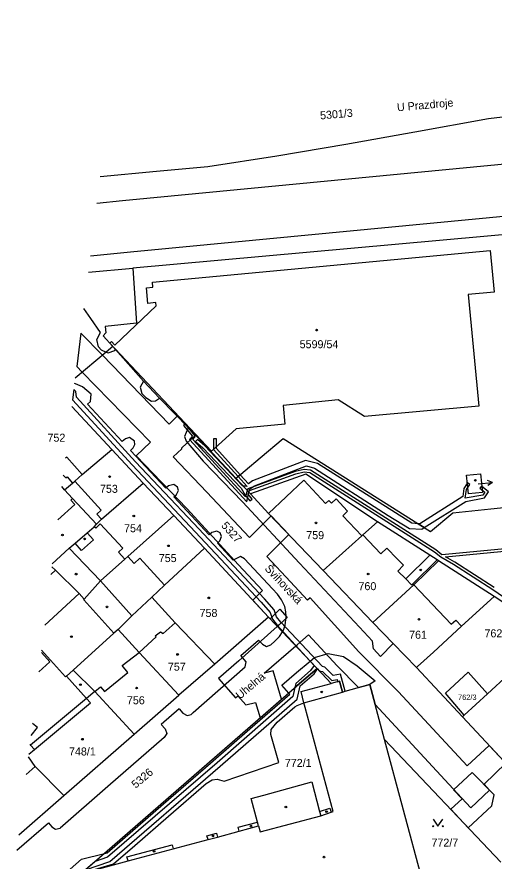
# Model space of a CAD drawing. Extents: x -821458 to -820266, y -1071458 to -1069826.
# Drawn here: x -821418.8 to -821317.4, y -1070028.3 to -1069849 of the extents above; entities that cross this region are included whole.
import ezdxf

# ---------------------------------------------------------------- set-up
doc = ezdxf.new("R2010")
doc.units = 0
for name, color, linetype in [('Vrstva 1', 7, 'Continuous'), ('Vrstva 13', 7, 'Continuous'), ('Vrstva 2', 7, 'Continuous'), ('Vrstva 3', 7, 'Continuous'), ('Vrstva 4', 7, 'Continuous'), ('Vrstva 5', 7, 'Continuous'), ('Vrstva 7', 7, 'Continuous')]:
    doc.layers.add(name, color=color, linetype=linetype)

msp = doc.modelspace()

# ---------------------------------------------------------------- linework, layer by layer
at = {"layer": 'Vrstva 1'}
for p, q in [((-821403.61, -1069903.25), (-821394.16, -1069902.36)), ((-821391.95, -1069948.02), (-821398.62, -1069940.91)), ((-821391.95, -1069948.02), (-821385.42, -1069954.95)), ((-821369.19, -1069950.3), (-821372.25, -1069947.02)), ((-821385.42, -1069954.95), (-821378.92, -1069961.87)), ((-821378.92, -1069961.87), (-821365.36, -1069976.5)), ((-821410.59, -1069966.54), (-821411.34, -1069965.82)), ((-821317.44, -1069972.1), (-821329.25, -1069964.52)), ((-821405.55, -1069971.52), (-821410.59, -1069966.54)), ((-821353.75, -1069966.62), (-821343.18, -1069977.68)), ((-821404.47, -1069972.7), (-821405.55, -1069971.52)), ((-821305.58, -1069979.99), (-821317.44, -1069972.1)), ((-821365.36, -1069976.5), (-821376.77, -1069986.5)), ((-821397.28, -1069979.17), (-821398.18, -1069979.89)), ((-821376.77, -1069986.5), (-821384.37, -1069993.11)), ((-821352.01, -1069990.61), (-821355.04, -1069987.4)), ((-821333.94, -1069987.23), (-821324.17, -1069997.7)), ((-821393.85, -1070001.36), (-821402.26, -1069992.33)), ((-821393.85, -1070001.36), (-821384.37, -1069993.11)), ((-821323.76, -1069997.32), (-821318.87, -1069992.82)), ((-821324.17, -1069997.7), (-821323.76, -1069997.32)), ((-821324.17, -1069997.7), (-821315.23, -1070007.23)), ((-821408.79, -1070014.39), (-821393.85, -1070001.36)), ((-821332.49, -1070033), (-821340.69, -1070002.53)), ((-821340.69, -1070002.53), (-821315.99, -1070028.55)), ((-821418.38, -1070022.73), (-821408.79, -1070014.39))]:
    msp.add_line(p, q, dxfattribs=at)
for points in [[(-821401.79, -1069888.55), (-821396.38, -1069888.03), (-821301.11, -1069878.88), (-821163.06, -1069864.6), (-821108.67, -1069859.31), (-821104.19, -1069858.87), (-821101.19, -1069858.58), (-821096.14, -1069858.08), (-821092.87, -1069856.06), (-821092.18, -1069852.96), (-821094.27, -1069849.73), (-821097.25, -1069848.99), (-821101.9, -1069849.39), (-821105.19, -1069849.71), (-821109.73, -1069850.16), (-821251.45, -1069864.02), (-821303.1, -1069868.83), (-821318.66, -1069870.67)], [(-821318.66, -1069870.67), (-821334.3, -1069873.5), (-821348.89, -1069876.11), (-821363.55, -1069878.57), (-821378.22, -1069880.82), (-821389.11, -1069881.81), (-821401.09, -1069882.94)], [(-821285.17, -1069885.29), (-821310.26, -1069890.87), (-821394.68, -1069899), (-821403.18, -1069899.82)], [(-821274.54, -1069891.39), (-821310.18, -1069894.83), (-821394.16, -1069902.36)], [(-821372.25, -1069947.02), (-821371.7, -1069946.55), (-821370.31, -1069945.37), (-821367.11, -1069942.65), (-821362.25, -1069938.53), (-821330.97, -1069958.32), (-821326.19, -1069954.35), (-821318.1, -1069953.51), (-821272.71, -1069948.78), (-821270.2, -1069948.52), (-821272.6, -1069916.85), (-821273.51, -1069904.81), (-821274.54, -1069891.39)], [(-821377.42, -1069941.26), (-821399.04, -1069918.28), (-821398.71, -1069917.97), (-821397.99, -1069918.75), (-821389.2, -1069910.41), (-821389.28, -1069909.67), (-821390.98, -1069909.85), (-821391.29, -1069906.56), (-821389.89, -1069906.42), (-821390.01, -1069905.33), (-821318.28, -1069898.6), (-821317.44, -1069907.44), (-821322.92, -1069907.95), (-821320.7, -1069931.68), (-821344.94, -1069933.92), (-821350.55, -1069930.35), (-821362.21, -1069931.55), (-821361.85, -1069935.51), (-821372.24, -1069936.49), (-821377.42, -1069941.26)], [(-821394.16, -1069902.36), (-821393.38, -1069914.05), (-821400.03, -1069914.8), (-821399.89, -1069916.08), (-821400.48, -1069916.76), (-821398.4, -1069918.99)], [(-821398.4, -1069918.99), (-821399.83, -1069920.19), (-821406.39, -1069925.76)], [(-821372.25, -1069947.02), (-821382.15, -1069936.43), (-821382.32, -1069936.26), (-821388.41, -1069930.08), (-821388.48, -1069930.01), (-821391.9, -1069926.38), (-821391.91, -1069926.37), (-821397.82, -1069919.65), (-821398.4, -1069918.99)], [(-821398.62, -1069940.91), (-821407.13, -1069931.73)], [(-821408.64, -1069949.45), (-821406.97, -1069948.02), (-821406.5, -1069947.6), (-821404.9, -1069946.18), (-821398.62, -1069940.91)], [(-821342.21, -1069956.25), (-821357.45, -1069946.12), (-821369.19, -1069950.3)], [(-821323.29, -1069946.33), (-821320.32, -1069946.04), (-821319.9, -1069950.01), (-821322.87, -1069950.32), (-821323.29, -1069946.33)], [(-821401.91, -1069956.78), (-821400.79, -1069955.71), (-821391.95, -1069948.02)], [(-821408.64, -1069949.45), (-821409.23, -1069948.73)], [(-821401.91, -1069956.78), (-821406.94, -1069951.3), (-821408.64, -1069949.45)], [(-821369.19, -1069950.3), (-821365.33, -1069954.47), (-821353.75, -1069966.62)], [(-821404.47, -1069972.7), (-821401.05, -1069968.8), (-821395.89, -1069964.17), (-821395.23, -1069963.62), (-821385.42, -1069954.95)], [(-821411.26, -1069965.17), (-821407.65, -1069961.87), (-821406.42, -1069960.8), (-821403.85, -1069958.63), (-821402.38, -1069957.29), (-821401.91, -1069956.78)], [(-821353.75, -1069966.62), (-821345.55, -1069959.22), (-821345.34, -1069959.01), (-821342.21, -1069956.25)], [(-821329.25, -1069964.52), (-821329.56, -1069964.32), (-821331.11, -1069963.33), (-821342.21, -1069956.25)], [(-821390.1, -1069972.3), (-821387.4, -1069969.7), (-821378.92, -1069961.87)], [(-821343.18, -1069977.68), (-821334.5, -1069969.62), (-821329.25, -1069964.52)], [(-821405.55, -1069971.52), (-821412.87, -1069978.21)], [(-821398.18, -1069979.89), (-821404.58, -1069972.8), (-821404.47, -1069972.7)], [(-821397.28, -1069979.17), (-821394.4, -1069976.2), (-821390.1, -1069972.3)], [(-821376.77, -1069986.5), (-821385.2, -1069977.7), (-821390.1, -1069972.3)], [(-821333.94, -1069987.23), (-821333.72, -1069987.03), (-821330.34, -1069983.93), (-821324.37, -1069978.44), (-821317.44, -1069972.1)], [(-821355.04, -1069987.4), (-821356.49, -1069985.87), (-821362.4, -1069979.62), (-821365.36, -1069976.5)], [(-821343.18, -1069977.68), (-821338.9, -1069982.11), (-821333.94, -1069987.23)], [(-821398.18, -1069979.89), (-821406.81, -1069987.74), (-821402.26, -1069992.33)], [(-821384.37, -1069993.11), (-821392.8, -1069984), (-821397.28, -1069979.17)], [(-821318.87, -1069992.82), (-821314.37, -1069988.68), (-821313.66, -1069988.01), (-821312.67, -1069987.07), (-821312.75, -1069986.99), (-821307.81, -1069982.16)], [(-821355.04, -1069987.4), (-821361.05, -1069992.64), (-821400.19, -1070026.71), (-821404.92, -1070030.82), (-821404.89, -1070030.92)], [(-821323.76, -1069997.32), (-821327.76, -1069992.69), (-821322.93, -1069988.19), (-821318.87, -1069992.82)], [(-821404.89, -1070030.92), (-821402.96, -1070030.39), (-821395.18, -1070028.26), (-821395.4, -1070027.44), (-821385.84, -1070024.9), (-821385.62, -1070025.72), (-821378.18, -1070023.74), (-821378.43, -1070022.94), (-821376.42, -1070022.4), (-821376.21, -1070023.22), (-821371.58, -1070021.98), (-821371.8, -1070021.15), (-821367.67, -1070020.04), (-821369.02, -1070015.05), (-821366.37, -1070014.32), (-821356.12, -1070011.49), (-821354.5, -1070017.79), (-821352.33, -1070017.08), (-821352.03, -1070017.97), (-821351.61, -1070017.83), (-821357.55, -1069995.73), (-821357.82, -1069994.73), (-821358.41, -1069992.32), (-821352.01, -1069990.61)], [(-821340.69, -1070002.53), (-821343.84, -1069990.8), (-821349.65, -1069992.42), (-821350.27, -1069990.14), (-821352.01, -1069990.61)], [(-821402.26, -1069992.33), (-821404.01, -1069993.8), (-821415.89, -1070003.68), (-821416.04, -1070003.8)], [(-821415.77, -1070001.64), (-821414.38, -1069999.94), (-821415.46, -1069999.13)], [(-821408.79, -1070014.39), (-821414.88, -1070008.21), (-821416.33, -1070006.21)]]:
    msp.add_lwpolyline(points, dxfattribs=at)
at = {"layer": 'Vrstva 13'}
for p, q in [((-821405.2, -1069916.17), (-821406.08, -1069923.26)), ((-821406.68, -1069928.15), (-821406.95, -1069930.33))]:
    msp.add_line(p, q, dxfattribs=at)
for points in [[(-821315.23, -1070007.23), (-821318.46, -1070003.79), (-821323.18, -1070008.11), (-821337.71, -1069992.41), (-821346.16, -1069983.88), (-821356.51, -1069972.43), (-821357.04, -1069972.88), (-821360.66, -1069969), (-821365.69, -1069963.6), (-821361.05, -1069958.96), (-821364.8, -1069955.02), (-821369.41, -1069959.62), (-821378.44, -1069949.97), (-821385.56, -1069942.43), (-821383.76, -1069940.73), (-821383.76, -1069940.51), (-821380.85, -1069937.82), (-821382.15, -1069936.43), (-821382.32, -1069936.26), (-821384.71, -1069933.83), (-821386.41, -1069935.5), (-821400.63, -1069920.87), (-821405.2, -1069916.17)], [(-821406.08, -1069923.26), (-821404.89, -1069924.49), (-821390.44, -1069939.36), (-821393.46, -1069942.27), (-821382.72, -1069953.45), (-821371.72, -1069965.41), (-821366.65, -1069970.87), (-821368.68, -1069972.92), (-821365.36, -1069976.5), (-821365.01, -1069976.87), (-821362.97, -1069974.82), (-821361.35, -1069976.57), (-821363.11, -1069978.14), (-821363.48, -1069978.48), (-821371.67, -1069985.81), (-821375.97, -1069989.56), (-821372.38, -1069993.68), (-821371.86, -1069993.22), (-821370.17, -1069995.16), (-821368.13, -1069994.62), (-821367.11, -1069997.91), (-821362.56, -1069993.96), (-821364.39, -1069987.89), (-821366.28, -1069988.4), (-821359.55, -1069982.63), (-821359.26, -1069982.38), (-821356.87, -1069980.26), (-821350.73, -1069986.88), (-821346.23, -1069991.47), (-821343.84, -1069990.8), (-821342.7, -1069995.04), (-821325.26, -1070013.87), (-821322.38, -1070016.99), (-821318.38, -1070013.29), (-821319.57, -1070012), (-821314.95, -1070007.52)], [(-821406.95, -1069930.33), (-821394.3, -1069944.17), (-821382, -1069957.24), (-821366.94, -1069973.3), (-821365.01, -1069975.49), (-821364.5, -1069976.91), (-821363.5, -1069978.2), (-821356.49, -1069985.87), (-821355.65, -1069986.76), (-821356.42, -1069987.84), (-821359.52, -1069990.59), (-821359.73, -1069991.49), (-821355.04, -1069987.4), (-821354.95, -1069987.5), (-821354.56, -1069987.91), (-821353.85, -1069988.05), (-821351.93, -1069990), (-821350.78, -1069989.79), (-821350.66, -1069990.25), (-821350.27, -1069990.14), (-821349.65, -1069992.42), (-821349.09, -1069992.26), (-821350.06, -1069988.63), (-821351.59, -1069988.92), (-821353.35, -1069987.13), (-821353.9, -1069987.02), (-821362.74, -1069977.56), (-821363.62, -1069976.43), (-821364.13, -1069974.97), (-821366.2, -1069972.62), (-821381.28, -1069956.56), (-821393.56, -1069943.49), (-821406.1, -1069929.8), (-821406.27, -1069928.59), (-821406.68, -1069928.15)], [(-821311.4, -1069961.64), (-821328.51, -1069963.24), (-821329.83, -1069962.21), (-821356.42, -1069945.3), (-821357.77, -1069945.15), (-821359.7, -1069945.6), (-821369.77, -1069949.22), (-821369.86, -1069949.58), (-821369.45, -1069950.02), (-821369.35, -1069949.6), (-821359.56, -1069946.08), (-821357.74, -1069945.65), (-821356.59, -1069945.78), (-821330.12, -1069962.61), (-821328.73, -1069963.71), (-821326.07, -1069965.25), (-821317.71, -1069970.63), (-821301.82, -1069981.55)], [(-821317.43, -1069970.21), (-821325.81, -1069964.83), (-821327.79, -1069963.68), (-821310.86, -1069962.1)]]:
    msp.add_lwpolyline(points, dxfattribs=at)
for points in [[(-821383.07, -1069935.5), (-821383.4, -1069935.82), (-821381.51, -1069938.07), (-821382.09, -1069938.79), (-821369.94, -1069951.98), (-821369.54, -1069949.93), (-821369.86, -1069949.58), (-821370.2, -1069950.96), (-821381.43, -1069938.77), (-821380.86, -1069938.07), (-821382.32, -1069936.26), (-821382.72, -1069935.86)], [(-821368.81, -1069951.45), (-821369.69, -1069950.38), (-821369.54, -1069949.93), (-821370.75, -1069948.63), (-821370.84, -1069948.62), (-821378.87, -1069940.09), (-821380.46, -1069938.75), (-821380.85, -1069939.21), (-821379.27, -1069940.55), (-821371.16, -1069949.14), (-821370.31, -1069950.58), (-821369.28, -1069951.83)], [(-821377.02, -1069938.6), (-821377.03, -1069940.9), (-821371.81, -1069946.64), (-821371.35, -1069946.25), (-821376.41, -1069940.69), (-821376.41, -1069940.33), (-821376.42, -1069938.6)], [(-821371.35, -1069946.25), (-821371.81, -1069946.64), (-821369.87, -1069948.77), (-821370.75, -1069948.63), (-821369.54, -1069949.93), (-821369.31, -1069949.27), (-821368.33, -1069948.59), (-821357.26, -1069944.35), (-821355.55, -1069944.87), (-821339.94, -1069954.9), (-821335.42, -1069957.66), (-821332.78, -1069957.79), (-821332.29, -1069957.49), (-821333.57, -1069956.67), (-821334.94, -1069956.57), (-821354.97, -1069943.87), (-821357.51, -1069943.24), (-821368.73, -1069947.53), (-821369.59, -1069948.18)], [(-821333.18, -1069956.7), (-821333.57, -1069956.67), (-821332.29, -1069957.49), (-821323.45, -1069951.92), (-821319.48, -1069951.16), (-821318.63, -1069949.86), (-821320.11, -1069948.67), (-821320.49, -1069949.13), (-821319.43, -1069949.98), (-821319.84, -1069950.62), (-821323.55, -1069951.22), (-821323.31, -1069949.4), (-821322.6, -1069948.33), (-821323.1, -1069948), (-821323.88, -1069949.18), (-821324.11, -1069950.86)], [(-821402.16, -1070028.42), (-821404.2, -1070030.19), (-821399.03, -1070028.39), (-821375.58, -1070008.2), (-821359.27, -1069993.93), (-821358.62, -1069991.13), (-821355.66, -1069988.52), (-821354.95, -1069987.5), (-821355.04, -1069987.4), (-821359.73, -1069991.49), (-821360.17, -1069993.39), (-821376.24, -1070007.44), (-821399.53, -1070027.51)], [(-821326.65, -1070017.33), (-821322.93, -1070021.24), (-821317.91, -1070016.61), (-821317.45, -1070014.27), (-821322.07, -1070009.5), (-821326.04, -1070013.21), (-821324.25, -1070015.12)]]:
    msp.add_lwpolyline(points, close=True, dxfattribs=at)
at = {"layer": 'Vrstva 3'}
msp.add_lwpolyline([(-821330.35, -1070019.44), (-821329.35, -1070020.94), (-821328.35, -1070019.44)], dxfattribs=at)
for centre in [(-821330.35, -1070020.94), (-821328.35, -1070020.94)]:
    msp.add_circle(centre, 0.1, dxfattribs=at)
at = {"layer": 'Vrstva 4'}
for p, q in [((-821403.07, -1069913.09), (-821404.56, -1069910.96)), ((-821401, -1069916.03), (-821403.07, -1069913.09)), ((-821401.83, -1069917.55), (-821401, -1069916.03)), ((-821401.43, -1069919.1), (-821401.83, -1069917.55)), ((-821400.9, -1069919.72), (-821401.43, -1069919.1)), ((-821400.9, -1069919.72), (-821399.83, -1069920.19)), ((-821399.83, -1069920.19), (-821399.37, -1069920.39)), ((-821408.21, -1069942.5), (-821408.49, -1069942.75)), ((-821404.9, -1069946.18), (-821408.21, -1069942.5)), ((-821408.93, -1069946.35), (-821408.4, -1069946.95)), ((-821408.4, -1069946.95), (-821408.13, -1069946.71)), ((-821408.13, -1069946.71), (-821406.97, -1069948.02)), ((-821400.9, -1069953.79), (-821406.5, -1069947.6)), ((-821365.33, -1069954.47), (-821357.83, -1069947.42)), ((-821357.83, -1069947.42), (-821353.22, -1069952.34)), ((-821407.31, -1069951.63), (-821406.94, -1069951.3)), ((-821406.48, -1069952.56), (-821407.31, -1069951.63)), ((-821353.22, -1069952.34), (-821352.55, -1069951.72)), ((-821352.55, -1069951.72), (-821351.98, -1069952.32)), ((-821351.98, -1069952.32), (-821350.99, -1069951.39)), ((-821350.99, -1069951.39), (-821348.54, -1069954.01)), ((-821410.1, -1069955.82), (-821406.48, -1069952.56)), ((-821401.83, -1069954.63), (-821400.9, -1069953.79)), ((-821400.79, -1069955.71), (-821401.83, -1069954.63)), ((-821348.54, -1069954.01), (-821349.56, -1069954.99)), ((-821349.56, -1069954.99), (-821345.55, -1069959.22)), ((-821401.07, -1069956.72), (-821402.05, -1069957.64)), ((-821396.27, -1069961.85), (-821401.07, -1069956.72)), ((-821403.85, -1069958.63), (-821402.51, -1069960.1)), ((-821402.05, -1069957.64), (-821402.38, -1069957.29)), ((-821345.34, -1069959.01), (-821341.47, -1069963.03)), ((-821405.05, -1069962.34), (-821406.42, -1069960.8)), ((-821402.51, -1069960.1), (-821405.05, -1069962.34)), ((-821407.65, -1069961.87), (-821401.05, -1069968.8)), ((-821397.22, -1069962.74), (-821396.27, -1069961.85)), ((-821341.47, -1069963.03), (-821340.25, -1069961.85)), ((-821340.25, -1069961.85), (-821338.04, -1069964.09)), ((-821395.89, -1069964.17), (-821397.22, -1069962.74)), ((-821393.86, -1069965.1), (-821395.23, -1069963.62)), ((-821392.7, -1069964.01), (-821393.86, -1069965.1)), ((-821387.4, -1069969.7), (-821392.7, -1069964.01)), ((-821338.04, -1069964.09), (-821336.65, -1069965.46)), ((-821336.21, -1069968.38), (-821331.11, -1069963.33)), ((-821329.56, -1069964.32), (-821334.71, -1069969.41)), ((-821336.65, -1069965.46), (-821337.85, -1069966.71)), ((-821411.54, -1069967.42), (-821410.59, -1069966.54)), ((-821337.85, -1069966.71), (-821336.21, -1069968.38)), ((-821401.05, -1069968.8), (-821394.4, -1069976.2)), ((-821336.21, -1069968.38), (-821334.96, -1069969.65)), ((-821334.96, -1069969.65), (-821334.71, -1069969.41)), ((-821334.71, -1069969.41), (-821334.5, -1069969.62)), ((-821334.5, -1069969.62), (-821326.56, -1069977.97)), ((-821361.66, -1069975.38), (-821361.91, -1069974.27)), ((-821361.81, -1069978.25), (-821361.6, -1069976.45)), ((-821361.6, -1069976.45), (-821361.66, -1069975.38)), ((-821387.7, -1069980), (-821385.2, -1069977.7)), ((-821362.19, -1069979.28), (-821361.81, -1069978.25)), ((-821326.56, -1069977.97), (-821325.57, -1069977.17)), ((-821325.57, -1069977.17), (-821324.37, -1069978.44)), ((-821389.4, -1069980.5), (-821388.3, -1069979.6)), ((-821389.2, -1069980.7), (-821389.4, -1069980.5)), ((-821388.3, -1069979.6), (-821387.7, -1069980)), ((-821363.04, -1069980.64), (-821362.4, -1069979.62)), ((-821362.4, -1069979.62), (-821362.19, -1069979.28)), ((-821392.8, -1069984), (-821389.2, -1069980.7)), ((-821371.23, -1069984.65), (-821367.47, -1069981.37)), ((-821367.47, -1069981.37), (-821366.65, -1069982.25)), ((-821366.65, -1069982.25), (-821365.76, -1069982.72)), ((-821364.87, -1069982.38), (-821364, -1069981.61)), ((-821364, -1069981.61), (-821363.04, -1069980.64)), ((-821408.44, -1069989.21), (-821413.53, -1069983.55)), ((-821396.44, -1069986.81), (-821392.8, -1069984)), ((-821365.76, -1069982.72), (-821364.87, -1069982.38)), ((-821370.06, -1069986), (-821371.23, -1069984.65)), ((-821406.81, -1069987.74), (-821408.27, -1069989.06)), ((-821395.25, -1069988.26), (-821396.44, -1069986.81)), ((-821381.35, -1069996.76), (-821370.29, -1069987.09)), ((-821370.29, -1069987.09), (-821370.06, -1069986)), ((-821408.27, -1069989.06), (-821408.44, -1069989.21)), ((-821404.01, -1069993.8), (-821408.27, -1069989.06)), ((-821400.18, -1069992.34), (-821395.25, -1069988.26)), ((-821402.26, -1069992.33), (-821401.01, -1069991.33)), ((-821401.01, -1069991.33), (-821400.18, -1069992.34)), ((-821357.82, -1069994.73), (-821349.65, -1069992.42)), ((-821415.07, -1070004.61), (-821403.13, -1069994.72)), ((-821403.13, -1069994.72), (-821404.01, -1069993.8)), ((-821384.29, -1069995.99), (-821383.53, -1069996.93)), ((-821383.53, -1069996.93), (-821382.6, -1069997.42)), ((-821382.6, -1069997.42), (-821381.8, -1069997.16)), ((-821381.8, -1069997.16), (-821381.35, -1069996.76)), ((-821377.66, -1070007.5), (-821369.34, -1070000.24)), ((-821416.01, -1070003.55), (-821415.89, -1070003.68)), ((-821415.89, -1070003.68), (-821415.07, -1070004.61)), ((-821416.26, -1070005.6), (-821415.07, -1070004.61)), ((-821416.79, -1070009.91), (-821414.88, -1070008.21)), ((-821387.65, -1070016.18), (-821377.66, -1070007.5)), ((-821399.45, -1070012.46), (-821409.57, -1070021.31)), ((-821399.58, -1070026.55), (-821387.65, -1070016.18)), ((-821354.5, -1070017.79), (-821354.26, -1070018.72)), ((-821354.26, -1070018.72), (-821352.03, -1070017.97)), ((-821367.1, -1070022.15), (-821354.26, -1070018.72)), ((-821371.58, -1070021.98), (-821367.44, -1070020.88)), ((-821367.44, -1070020.88), (-821367.67, -1070020.04)), ((-821367.44, -1070020.88), (-821367.1, -1070022.15)), ((-821378.18, -1070023.74), (-821376.21, -1070023.22)), ((-821405.05, -1070027.96), (-821400.19, -1070026.71)), ((-821400.19, -1070026.71), (-821399.58, -1070026.55)), ((-821395.18, -1070028.26), (-821385.62, -1070025.72))]:
    msp.add_line(p, q, dxfattribs=at)
for points in [[(-821399.37, -1069920.39), (-821397.99, -1069919.84), (-821397.82, -1069919.65)], [(-821391.9, -1069926.38), (-821392.62, -1069927.62), (-821392.24, -1069928.97), (-821391.42, -1069929.85), (-821390.23, -1069930.63), (-821389.35, -1069930.57), (-821388.48, -1069930.01)], [(-821403.77, -1069931.27), (-821403.16, -1069930.7), (-821403.01, -1069929.15), (-821404.87, -1069927.57), (-821406.36, -1069926.92), (-821406.53, -1069926.89)], [(-821361.91, -1069974.27), (-821362.59, -1069972.8), (-821363.44, -1069971.63), (-821364.5, -1069970.49), (-821370.44, -1069964.11), (-821371.26, -1069963.63), (-821372.84, -1069964.39), (-821376.21, -1069960.8), (-821375.68, -1069960.29), (-821375.31, -1069959.37), (-821375.62, -1069958.58), (-821376.32, -1069958.21), (-821377.41, -1069958.53), (-821377.92, -1069958.99), (-821385.44, -1069950.93), (-821384.91, -1069950.43), (-821384.49, -1069949.63), (-821384.69, -1069948.89), (-821385.45, -1069948.31), (-821386.6, -1069948.61), (-821387.13, -1069949.11), (-821394.62, -1069941.09), (-821394.08, -1069940.56), (-821393.72, -1069939.83), (-821393.84, -1069939.13), (-821394.86, -1069938.38), (-821395.71, -1069938.63), (-821396.39, -1069939.21), (-821403.77, -1069931.27)], [(-821382.32, -1069936.26), (-821382.49, -1069936.42), (-821383.19, -1069938.15), (-821382.82, -1069939.16), (-821379.19, -1069943.38), (-821370.84, -1069951.99)], [(-821338.9, -1069982.11), (-821341.56, -1069984.86), (-821343.05, -1069983.23), (-821343.24, -1069981.59), (-821346.03, -1069978.62), (-821358.74, -1069965.01), (-821370.84, -1069951.99)], [(-821414.1, -1069988.1), (-821411.77, -1069986.01), (-821413.59, -1069984)], [(-821361.05, -1069992.64), (-821362.5, -1069990.96), (-821359.43, -1069988.3), (-821356.49, -1069985.87)], [(-821356.49, -1069985.87), (-821355.56, -1069985.1), (-821352.66, -1069984.24), (-821349.44, -1069984.86), (-821346.49, -1069986.88), (-821342.7, -1069990.06), (-821343.84, -1069990.8)], [(-821369.34, -1070000.24), (-821360.85, -1069992.87), (-821361.05, -1069992.64)], [(-821378.62, -1070011.87), (-821377.28, -1070011.08), (-821376.26, -1070010.95), (-821374.76, -1070011.39), (-821363.14, -1070007.42), (-821364.82, -1070001.47), (-821364.77, -1070000.4), (-821363.51, -1069998.83), (-821359.74, -1069995.55), (-821359.25, -1069995.3), (-821357.82, -1069994.73)], [(-821384.29, -1069995.99), (-821388.14, -1069999.35), (-821387.3, -1070000.27), (-821386.95, -1070001.25), (-821387.48, -1070002.07), (-821399.45, -1070012.46)], [(-821404.89, -1070030.92), (-821398.27, -1070028.95), (-821393.72, -1070024.99), (-821386.56, -1070018.77), (-821378.62, -1070011.87)], [(-821418.78, -1070026.01), (-821412.1, -1070020.18), (-821411.35, -1070021.09), (-821410.56, -1070021.58), (-821409.57, -1070021.31)], [(-821405.05, -1070027.96), (-821410.53, -1070032.73), (-821411.84, -1070034.93), (-821411.87, -1070035.32)]]:
    msp.add_lwpolyline(points, dxfattribs=at)
at = {"layer": 'Vrstva 5'}
for centre in [(-821355.13, -1069915.54), (-821399.08, -1069946.65), (-821321.41, -1069947.43), (-821393.96, -1069955.02), (-821355.27, -1069956.49), (-821409.11, -1069959.06), (-821404.39, -1069959.89), (-821386.59, -1069961.36), (-821406.21, -1069967.37), (-821344.18, -1069967.33), (-821333.03, -1069966.49), (-821378.03, -1069972.42), (-821399.63, -1069974.33), (-821333.39, -1069976.96), (-821407.2, -1069980.65), (-821384.66, -1069984.43), (-821405.28, -1069990.84), (-821393.36, -1069991.57), (-821354.05, -1069992.4), (-821404.86, -1070002.45), (-821361.65, -1070016.85), (-821353.02, -1070017.85), (-821369.08, -1070020.9), (-821377.15, -1070022.99), (-821389.64, -1070026.27), (-821353.56, -1070027.49)]:
    msp.add_circle(centre, 0.175, dxfattribs=at)
at = {"layer": 'Vrstva 7'}
for p, q in [((-821320.8, -1069948.18), (-821317.81, -1069947.92)), ((-821317.81, -1069947.92), (-821318.85, -1069947.51)), ((-821317.81, -1069947.92), (-821318.76, -1069948.51))]:
    msp.add_line(p, q, dxfattribs=at)

# ---------------------------------------------------------------- texts
at = {"layer": 'Vrstva 2'}
for s, rotation, p in [('5301/3', 5, (-821354.32, -1069870.79)), ('5327', 312, (-821375.5, -1069957.14)), ('5326', 40, (-821393.56, -1070012.98))]:
    msp.add_text(s, height=1.7, rotation=rotation, dxfattribs=at).set_placement(p)
for s, height, p in [('5599/54', 1.7, (-821358.73, -1069919.38)), ('752', 1.7, (-821412.29, -1069939.24)), ('753', 1.7, (-821401.14, -1069950.1)), ('754', 1.7, (-821396.02, -1069958.47)), ('759', 1.7, (-821357.33, -1069959.94)), ('755', 1.7, (-821388.65, -1069964.81)), ('760', 1.7, (-821346.24, -1069970.78)), ('758', 1.7, (-821379.99, -1069976.47)), ('761', 1.7, (-821335.49, -1069981.1)), ('762/1', 1.7, (-821319.48, -1069980.8)), ('757', 1.7, (-821386.72, -1069987.88)), ('762/3', 1.139, (-821325.1, -1069994.1)), ('756', 1.7, (-821395.42, -1069995.02)), ('748/1', 1.7, (-821407.72, -1070005.9)), ('772/1', 1.7, (-821361.88, -1070008.33)), ('772/7', 1.7, (-821330.74, -1070025.26))]:
    msp.add_text(s, height=height, dxfattribs=at).set_placement(p)
at = {"layer": 'Vrstva 7'}
for s, rotation, p in [('U Prazdroje', 5, (-821337.99, -1069869.06)), ('Švihovská', 313, (-821366.27, -1069966.3)), ('Uhelná', 40, (-821371.41, -1069994.05))]:
    msp.add_text(s, height=1.7, rotation=rotation, dxfattribs=at).set_placement(p)

doc.saveas('drawing.dxf')
